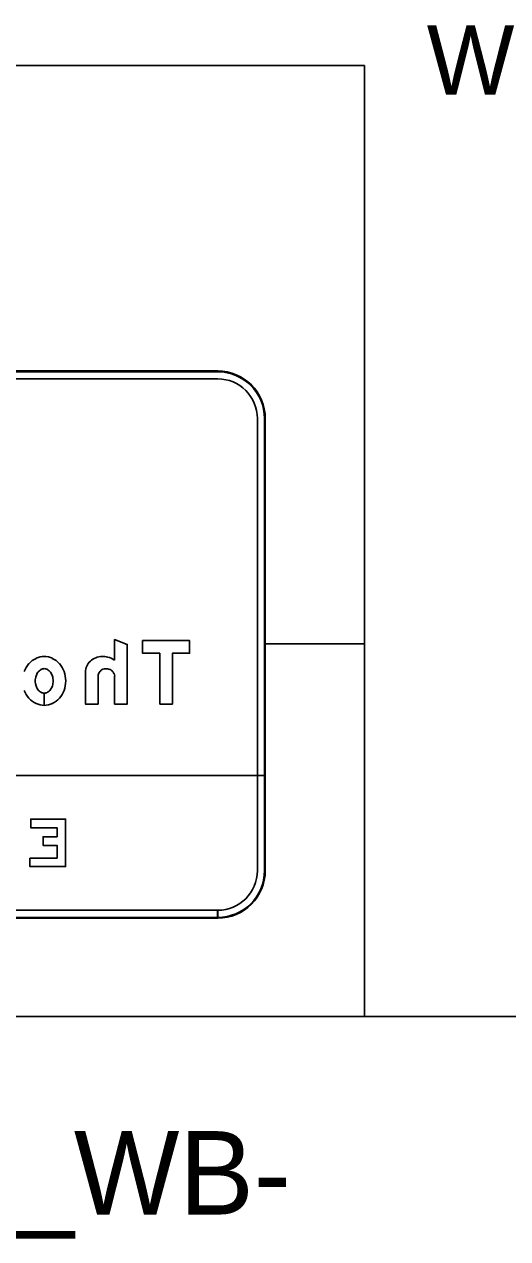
# Model space of a CAD drawing. Extents: x 1726582 to 1728895, y 538986 to 541550.
# Drawn here: x 1727216.6 to 1727265.4, y 541422.6 to 541545.1 of the extents above; entities that cross this region are included whole.
import ezdxf

# ---------------------------------------------------------------- set-up
doc = ezdxf.new("R2010")
doc.units = 0
for name, color, linetype in [('Default', 7, 'Continuous'), ('GSProposed', 7, 'Continuous'), ('GSRemove', 7, 'Continuous'), ('Old_Level_2', 7, 'Continuous')]:
    doc.layers.add(name, color=color, linetype=linetype)

msp = doc.modelspace()

# ---------------------------------------------------------------- linework, layer by layer
at = {"layer": 'Default'}
for p, q in [((1727137.33, 541540.92), (1727250.93, 541540.92)), ((1727250.93, 541540.92), (1727250.93, 541445)), ((1727240.93, 541482.6), (1727250.93, 541482.6)), ((1727137.33, 541445), (1727250.93, 541445)), ((1727250.93, 541445), (1727880.5, 541445))]:
    msp.add_line(p, q, dxfattribs=at)
at = {"layer": 'Old_Level_2'}
for p, q in [((1727152.13, 541510.12), (1727236.13, 541510.12)), ((1727152.13, 541510.12), (1727236.13, 541510.12)), ((1727152.13, 541510.12), (1727236.13, 541510.12)), ((1727152.13, 541510.12), (1727236.13, 541510.12)), ((1727152.13, 541510.12), (1727236.13, 541510.12)), ((1727236.13, 541510.04), (1727152.13, 541510.04)), ((1727152.13, 541509.32), (1727236.13, 541509.32)), ((1727236.13, 541509.32), (1727152.13, 541509.32)), ((1727236.13, 541509.32), (1727152.13, 541509.32)), ((1727240.13, 541505.32), (1727240.13, 541459.72)), ((1727240.13, 541459.72), (1727240.13, 541505.32)), ((1727240.13, 541459.72), (1727240.13, 541505.32)), ((1727240.85, 541459.72), (1727240.85, 541505.32)), ((1727240.93, 541505.32), (1727240.93, 541459.72)), ((1727240.93, 541505.32), (1727240.93, 541459.72)), ((1727240.93, 541505.32), (1727240.93, 541459.72)), ((1727240.93, 541505.32), (1727240.93, 541459.72)), ((1727240.93, 541505.32), (1727240.93, 541459.72)), ((1727218.64, 541476.39), (1727218.64, 541477.62)), ((1727218.64, 541477.62), (1727218.64, 541476.39)), ((1727218.64, 541476.39), (1727218.64, 541477.62)), ((1727218.64, 541477.62), (1727218.64, 541476.39)), ((1727147.33, 541469.32), (1727240.93, 541469.32)), ((1727147.33, 541469.32), (1727240.93, 541469.32)), ((1727147.33, 541469.32), (1727240.93, 541469.32)), ((1727240.93, 541469.32), (1727240.13, 541469.32)), ((1727240.13, 541469.32), (1727240.13, 541468.52)), ((1727240.93, 541469.32), (1727240.13, 541469.32)), ((1727240.13, 541469.32), (1727240.13, 541468.52)), ((1727240.93, 541469.32), (1727240.13, 541469.32)), ((1727240.13, 541469.32), (1727240.13, 541468.52)), ((1727240.93, 541469.32), (1727240.85, 541469.32)), ((1727240.85, 541469.32), (1727240.85, 541469.24)), ((1727240.85, 541469.24), (1727240.85, 541459.72)), ((1727240.93, 541469.32), (1727240.93, 541459.72)), ((1727240.93, 541459.72), (1727240.93, 541469.32)), ((1727240.93, 541459.72), (1727240.93, 541469.32)), ((1727240.93, 541459.72), (1727240.93, 541469.32)), ((1727240.93, 541469.32), (1727240.93, 541459.72)), ((1727240.93, 541469.32), (1727240.93, 541459.72)), ((1727240.93, 541459.72), (1727240.93, 541469.32)), ((1727240.13, 541468.52), (1727240.13, 541459.72)), ((1727240.13, 541468.52), (1727240.13, 541459.72)), ((1727240.13, 541468.52), (1727240.13, 541459.72)), ((1727236.13, 541455.72), (1727152.13, 541455.72)), ((1727236.13, 541455.72), (1727152.13, 541455.72)), ((1727236.13, 541455.72), (1727152.13, 541455.72)), ((1727236.13, 541455.72), (1727152.13, 541455.72)), ((1727152.13, 541455.72), (1727236.12, 541455.72)), ((1727152.13, 541455.72), (1727236.12, 541455.72)), ((1727236.12, 541455.72), (1727236.12, 541454.92)), ((1727236.12, 541455.72), (1727236.12, 541454.92)), ((1727236.13, 541454.92), (1727236.13, 541455.72)), ((1727236.13, 541454.92), (1727236.13, 541455.72)), ((1727236.13, 541455), (1727152.13, 541455)), ((1727152.13, 541455), (1727236.13, 541455)), ((1727236.13, 541454.92), (1727152.13, 541454.92)), ((1727152.13, 541454.92), (1727236.13, 541454.92)), ((1727152.13, 541454.92), (1727236.13, 541454.92)), ((1727152.13, 541454.92), (1727236.13, 541454.92)), ((1727236.13, 541454.92), (1727152.13, 541454.92)), ((1727236.13, 541454.92), (1727152.13, 541454.92)), ((1727152.13, 541454.92), (1727236.13, 541454.92)), ((1727236.13, 541454.92), (1727152.13, 541454.92)), ((1727236.13, 541454.92), (1727152.13, 541454.92)), ((1727236.12, 541454.92), (1727152.13, 541454.92)), ((1727236.12, 541454.92), (1727152.13, 541454.92)), ((1727236.13, 541454.92), (1727152.13, 541454.92)), ((1727236.13, 541454.92), (1727236.13, 541455)), ((1727236.13, 541455), (1727236.13, 541454.92))]:
    msp.add_line(p, q, dxfattribs=at)
for points in [[(1727225.74, 541480.96), (1727225.74, 541483.03), (1727227.02, 541482.54), (1727227.02, 541476.52), (1727225.74, 541476.52), (1727225.74, 541479.33)], [(1727225.74, 541480.96), (1727225.74, 541483.03), (1727227.02, 541482.54), (1727227.02, 541476.52), (1727225.74, 541476.52), (1727225.74, 541479.33)], [(1727225.74, 541480.96), (1727225.74, 541483.03), (1727227.02, 541482.54), (1727227.02, 541476.52), (1727225.74, 541476.52), (1727225.74, 541479.33)], [(1727224.08, 541479.33), (1727224.08, 541476.52), (1727222.8, 541476.52), (1727222.8, 541479.75)], [(1727224.08, 541479.33), (1727224.08, 541476.52), (1727222.8, 541476.52), (1727222.8, 541479.75)], [(1727224.08, 541479.33), (1727224.08, 541476.52), (1727222.8, 541476.52), (1727222.8, 541479.75)]]:
    msp.add_lwpolyline(points, dxfattribs=at)
for points in [[(1727230.29, 541476.52), (1727231.57, 541476.52), (1727231.57, 541481.64), (1727233.29, 541481.64), (1727233.29, 541482.92), (1727228.56, 541482.92), (1727228.56, 541481.64), (1727230.29, 541481.64)], [(1727230.29, 541476.52), (1727231.57, 541476.52), (1727231.57, 541481.64), (1727233.29, 541481.64), (1727233.29, 541482.92), (1727228.56, 541482.92), (1727228.56, 541481.64), (1727230.29, 541481.64)], [(1727230.29, 541476.52), (1727231.57, 541476.52), (1727231.57, 541481.64), (1727233.29, 541481.64), (1727233.29, 541482.92), (1727228.56, 541482.92), (1727228.56, 541481.64), (1727230.29, 541481.64)], [(1727217.2, 541460.98), (1727219.94, 541460.98), (1727219.94, 541462.27), (1727218.52, 541462.27), (1727218.52, 541463.14), (1727219.94, 541463.14), (1727219.94, 541464.05), (1727217.28, 541464.05), (1727217.28, 541464.92), (1727220.8, 541464.92), (1727220.8, 541460.12), (1727217.2, 541460.12)], [(1727217.2, 541460.98), (1727219.94, 541460.98), (1727219.94, 541462.27), (1727218.52, 541462.27), (1727218.52, 541463.14), (1727219.94, 541463.14), (1727219.94, 541464.05), (1727217.28, 541464.05), (1727217.28, 541464.92), (1727220.8, 541464.92), (1727220.8, 541460.12), (1727217.2, 541460.12)], [(1727217.2, 541460.98), (1727219.94, 541460.98), (1727219.94, 541462.27), (1727218.52, 541462.27), (1727218.52, 541463.14), (1727219.94, 541463.14), (1727219.94, 541464.05), (1727217.28, 541464.05), (1727217.28, 541464.92), (1727220.8, 541464.92), (1727220.8, 541460.12), (1727217.2, 541460.12)]]:
    msp.add_lwpolyline(points, close=True, dxfattribs=at)
for centre, radius, start, end in [((1727236.13, 541505.32), 4.8, 0, 90), ((1727236.13, 541505.32), 4.8, 0, 90), ((1727236.13, 541505.32), 4.8, 0, 90), ((1727236.13, 541505.32), 4.8, 0, 90), ((1727236.13, 541505.32), 4.8, 0, 90), ((1727236.13, 541505.32), 4.72, 0, 90), ((1727236.13, 541505.32), 4, 0, 90), ((1727236.13, 541505.32), 4, 0, 90), ((1727236.13, 541505.32), 4, 0, 90), ((1727224.27, 541479.75), 1.47, 156.0683, 180), ((1727224.27, 541479.75), 1.47, 156.0683, 180), ((1727224.27, 541479.75), 1.47, 156.0683, 180), ((1727224.37, 541479.7), 1.58, 133.025, 156.0683), ((1727224.37, 541479.7), 1.58, 133.025, 156.0683), ((1727224.37, 541479.7), 1.58, 133.025, 156.0683), ((1727224.44, 541479.63), 1.68, 111.1364, 133.025), ((1727224.44, 541479.63), 1.68, 111.1364, 133.025), ((1727224.44, 541479.63), 1.68, 111.1364, 133.025), ((1727224.48, 541479.52), 1.8, 90, 111.1364), ((1727224.48, 541479.52), 1.8, 90, 111.1364), ((1727224.48, 541479.52), 1.8, 90, 111.1364), ((1727224.48, 541478.76), 2.56, 77.3957, 90), ((1727224.48, 541478.76), 2.56, 77.3957, 90), ((1727224.48, 541478.76), 2.56, 77.3957, 90), ((1727224.5, 541479.02), 2.3, 57.5057, 76.5305), ((1727224.5, 541479.02), 2.3, 57.5057, 76.5305), ((1727224.5, 541479.02), 2.3, 57.5057, 76.5305), ((1727224.82, 541479.33), 0.742, 156.9072, 180), ((1727224.82, 541479.33), 0.742, 156.9072, 180), ((1727224.82, 541479.33), 0.742, 156.9072, 180), ((1727224.84, 541479.32), 0.765, 134.1702, 156.9072), ((1727224.84, 541479.32), 0.765, 134.1702, 156.9072), ((1727224.84, 541479.32), 0.765, 134.1702, 156.9072), ((1727224.86, 541479.3), 0.785, 111.9192, 134.1702), ((1727224.86, 541479.3), 0.785, 111.9192, 134.1702), ((1727224.86, 541479.3), 0.785, 111.9192, 134.1702), ((1727224.86, 541479.28), 0.809, 90, 111.9192), ((1727224.86, 541479.28), 0.809, 90, 111.9192), ((1727224.86, 541479.28), 0.809, 90, 111.9192), ((1727224.86, 541479.08), 1.01, 70.1926, 90), ((1727224.86, 541479.08), 1.01, 70.1926, 90), ((1727224.86, 541479.08), 1.01, 70.1926, 90), ((1727224.91, 541479.2), 0.881, 48.9924, 70.1926), ((1727224.91, 541479.2), 0.881, 48.9924, 70.1926), ((1727224.91, 541479.2), 0.881, 48.9924, 70.1926), ((1727224.97, 541479.28), 0.78, 25.4717, 48.9924), ((1727224.97, 541479.28), 0.78, 25.4717, 48.9924), ((1727224.97, 541479.28), 0.78, 25.4717, 48.9924), ((1727225.08, 541479.33), 0.667, 0, 25.4717), ((1727225.08, 541479.33), 0.667, 0, 25.4717), ((1727225.08, 541479.33), 0.667, 0, 25.4717), ((1727236.13, 541459.72), 4.8, 270, 0), ((1727236.13, 541459.72), 4.8, 270, 0), ((1727236.13, 541459.72), 4, 270, 0), ((1727236.13, 541459.72), 4.8, 270, 0), ((1727236.13, 541459.72), 4, 270, 0), ((1727236.13, 541459.72), 4.8, 270, 0), ((1727236.13, 541459.72), 4, 270, 0), ((1727236.13, 541459.72), 4.8, 270, 0), ((1727236.13, 541459.72), 4.8, 270, 0), ((1727236.13, 541459.72), 4.8, 270, 0), ((1727236.13, 541459.72), 4.72, 270, 0), ((1727236.13, 541459.72), 4.8, 270, 0), ((1727236.13, 541459.72), 4.8, 270, 0), ((1727236.13, 541459.72), 4, 270, 0), ((1727236.13, 541459.72), 4.8, 270, 0), ((1727236.13, 541459.72), 4, 270, 0), ((1727236.13, 541459.72), 4.8, 270, 0), ((1727236.13, 541459.72), 4, 270, 0), ((1727236.13, 541459.72), 4.8, 270, 0), ((1727236.13, 541459.72), 4.72, 270, 0)]:
    msp.add_arc(centre, radius, start, end, dxfattribs=at)
for centre, major_axis, start_param, end_param in [((1727218.95, 541478.96), (0, -2.47), 3.98898, 4.361709), ((1727218.95, 541478.96), (0, -2.47), 3.98898, 4.361709), ((1727218.95, 541478.96), (0, -2.47), 3.98898, 4.361709), ((1727218.76, 541479.13), (0, -2.21), 3.580164, 3.98898), ((1727218.76, 541479.13), (0, -2.21), 3.580164, 3.98898), ((1727218.76, 541479.13), (0, -2.21), 3.580164, 3.98898), ((1727218.64, 541479.39), (0, -1.93), 3.141593, 3.580164), ((1727218.64, 541479.39), (0, -1.93), 3.141593, 3.580164), ((1727218.64, 541479.39), (0, -1.93), 3.141593, 3.580164), ((1727218.64, 541479.39), (0, -1.93), 2.703022, 3.141593), ((1727218.64, 541479.39), (0, -1.93), 2.703022, 3.141593), ((1727218.64, 541479.39), (0, -1.93), 2.703022, 3.141593), ((1727218.52, 541479.13), (0, -2.21), 2.294205, 2.703022), ((1727218.52, 541479.13), (0, -2.21), 2.294205, 2.703022), ((1727218.52, 541479.13), (0, -2.21), 2.294205, 2.703022), ((1727218.33, 541478.96), (0, -2.47), 1.921476, 2.294205), ((1727218.33, 541478.96), (0, -2.47), 1.921476, 2.294205), ((1727218.33, 541478.96), (0, -2.47), 1.921476, 2.294205), ((1727219.43, 541478.85), (0, -1.69), 4.419789, 4.712389), ((1727219.43, 541478.85), (0, -1.69), 4.419789, 4.712389), ((1727219.43, 541478.85), (0, -1.69), 4.419789, 4.712389), ((1727219.04, 541478.97), (0, -1.28), 4.083593, 4.419789), ((1727219.04, 541478.97), (0, -1.28), 4.083593, 4.419789), ((1727219.04, 541478.97), (0, -1.28), 4.083593, 4.419789), ((1727218.8, 541479.15), (0, -0.977), 3.659317, 4.083593), ((1727218.8, 541479.15), (0, -0.977), 3.659317, 4.083593), ((1727218.8, 541479.15), (0, -0.977), 3.659317, 4.083593), ((1727218.64, 541479.43), (0, -0.661), 3.141593, 3.659317), ((1727218.64, 541479.43), (0, -0.661), 3.141593, 3.659317), ((1727218.64, 541479.43), (0, -0.661), 3.141593, 3.659317), ((1727218.64, 541479.43), (0, -0.661), 2.623869, 3.141593), ((1727218.64, 541479.43), (0, -0.661), 2.623869, 3.141593), ((1727218.64, 541479.43), (0, -0.661), 2.623869, 3.141593), ((1727218.48, 541479.15), (0, -0.977), 2.199593, 2.623869), ((1727218.48, 541479.15), (0, -0.977), 2.199593, 2.623869), ((1727218.48, 541479.15), (0, -0.977), 2.199593, 2.623869), ((1727218.24, 541478.97), (0, -1.28), 1.863396, 2.199593), ((1727218.24, 541478.97), (0, -1.28), 1.863396, 2.199593), ((1727218.24, 541478.97), (0, -1.28), 1.863396, 2.199593), ((1727217.85, 541478.85), (0, -1.69), 1.570796, 1.863396), ((1727217.85, 541478.85), (0, -1.69), 1.570796, 1.863396), ((1727217.85, 541478.85), (0, -1.69), 1.570796, 1.863396), ((1727218.03, 541478.85), (0, -2.78), 1.570796, 1.921476), ((1727218.03, 541478.85), (0, -2.78), 1.570796, 1.921476), ((1727218.03, 541478.85), (0, -2.78), 1.570796, 1.921476), ((1727218.95, 541478.75), (0, -2.47), 5.063069, 5.435798), ((1727218.95, 541478.75), (0, -2.47), 5.063069, 5.435798), ((1727218.95, 541478.75), (0, -2.47), 5.063069, 5.435798), ((1727219.43, 541478.85), (0, -1.69), 4.712389, 5.004989), ((1727219.43, 541478.85), (0, -1.69), 4.712389, 5.004989), ((1727219.43, 541478.85), (0, -1.69), 4.712389, 5.004989), ((1727219.04, 541478.74), (0, -1.28), 5.004989, 5.341185), ((1727219.04, 541478.74), (0, -1.28), 5.004989, 5.341185), ((1727219.04, 541478.74), (0, -1.28), 5.004989, 5.341185), ((1727218.8, 541478.56), (0, -0.977), 5.341185, 5.765461), ((1727218.8, 541478.56), (0, -0.977), 5.341185, 5.765461), ((1727218.8, 541478.56), (0, -0.977), 5.341185, 5.765461), ((1727218.48, 541478.56), (0, -0.977), 0.517724, 0.942), ((1727218.48, 541478.56), (0, -0.977), 0.517724, 0.942), ((1727218.48, 541478.56), (0, -0.977), 0.517724, 0.942), ((1727218.24, 541478.74), (0, -1.28), 0.942, 1.278197), ((1727218.24, 541478.74), (0, -1.28), 0.942, 1.278197), ((1727218.24, 541478.74), (0, -1.28), 0.942, 1.278197), ((1727217.85, 541478.85), (0, -1.69), 1.278197, 1.570796), ((1727217.85, 541478.85), (0, -1.69), 1.278197, 1.570796), ((1727217.85, 541478.85), (0, -1.69), 1.278197, 1.570796), ((1727218.33, 541478.75), (0, -2.47), 0.847388, 1.220117), ((1727218.33, 541478.75), (0, -2.47), 0.847388, 1.220117), ((1727218.33, 541478.75), (0, -2.47), 0.847388, 1.220117), ((1727218.03, 541478.85), (0, -2.78), 1.220117, 1.570796), ((1727218.03, 541478.85), (0, -2.78), 1.220117, 1.570796), ((1727218.03, 541478.85), (0, -2.78), 1.220117, 1.570796), ((1727218.76, 541478.58), (0, -2.21), 5.435798, 5.844614), ((1727218.76, 541478.58), (0, -2.21), 5.435798, 5.844614), ((1727218.76, 541478.58), (0, -2.21), 5.435798, 5.844614), ((1727218.64, 541478.32), (0, -1.93), 5.844614, 6.283185), ((1727218.64, 541478.32), (0, -1.93), 5.844614, 6.283019), ((1727218.64, 541478.32), (0, -1.93), 5.844614, 6.283019), ((1727218.64, 541478.28), (0, -0.661), 5.765461, 6.283185), ((1727218.64, 541478.28), (0, -0.661), 5.765461, 6.282701), ((1727218.64, 541478.28), (0, -0.661), 5.765461, 6.282701), ((1727218.64, 541478.28), (0, -0.661), 0, 0.517724), ((1727218.64, 541478.28), (0, -0.661), 0, 0.517724), ((1727218.64, 541478.28), (0, -0.661), 0, 0.517724), ((1727218.64, 541478.32), (0, -1.93), 6.283185, 6.721756), ((1727218.64, 541478.32), (0, -1.93), 0, 0.438571), ((1727218.64, 541478.32), (0, -1.93), 0, 0.438571), ((1727218.52, 541478.58), (0, -2.21), 0.438571, 0.847388), ((1727218.52, 541478.58), (0, -2.21), 0.438571, 0.847388), ((1727218.52, 541478.58), (0, -2.21), 0.438571, 0.847388)]:
    msp.add_ellipse(centre, major_axis=major_axis, ratio=0.999993, start_param=start_param, end_param=end_param, dxfattribs=at)

# ---------------------------------------------------------------- texts
at = {"layer": 'GSProposed'}
msp.add_text('WINDLOAD AREA: 282" X 234"', height=7.0055, dxfattribs=at).set_placement((1727257.21, 541537.98))
at = {"layer": 'GSRemove'}
msp.add_text('-L_WB-', height=8.421, dxfattribs=at).set_placement((1727205.36, 541425.03))

doc.saveas('drawing.dxf')
